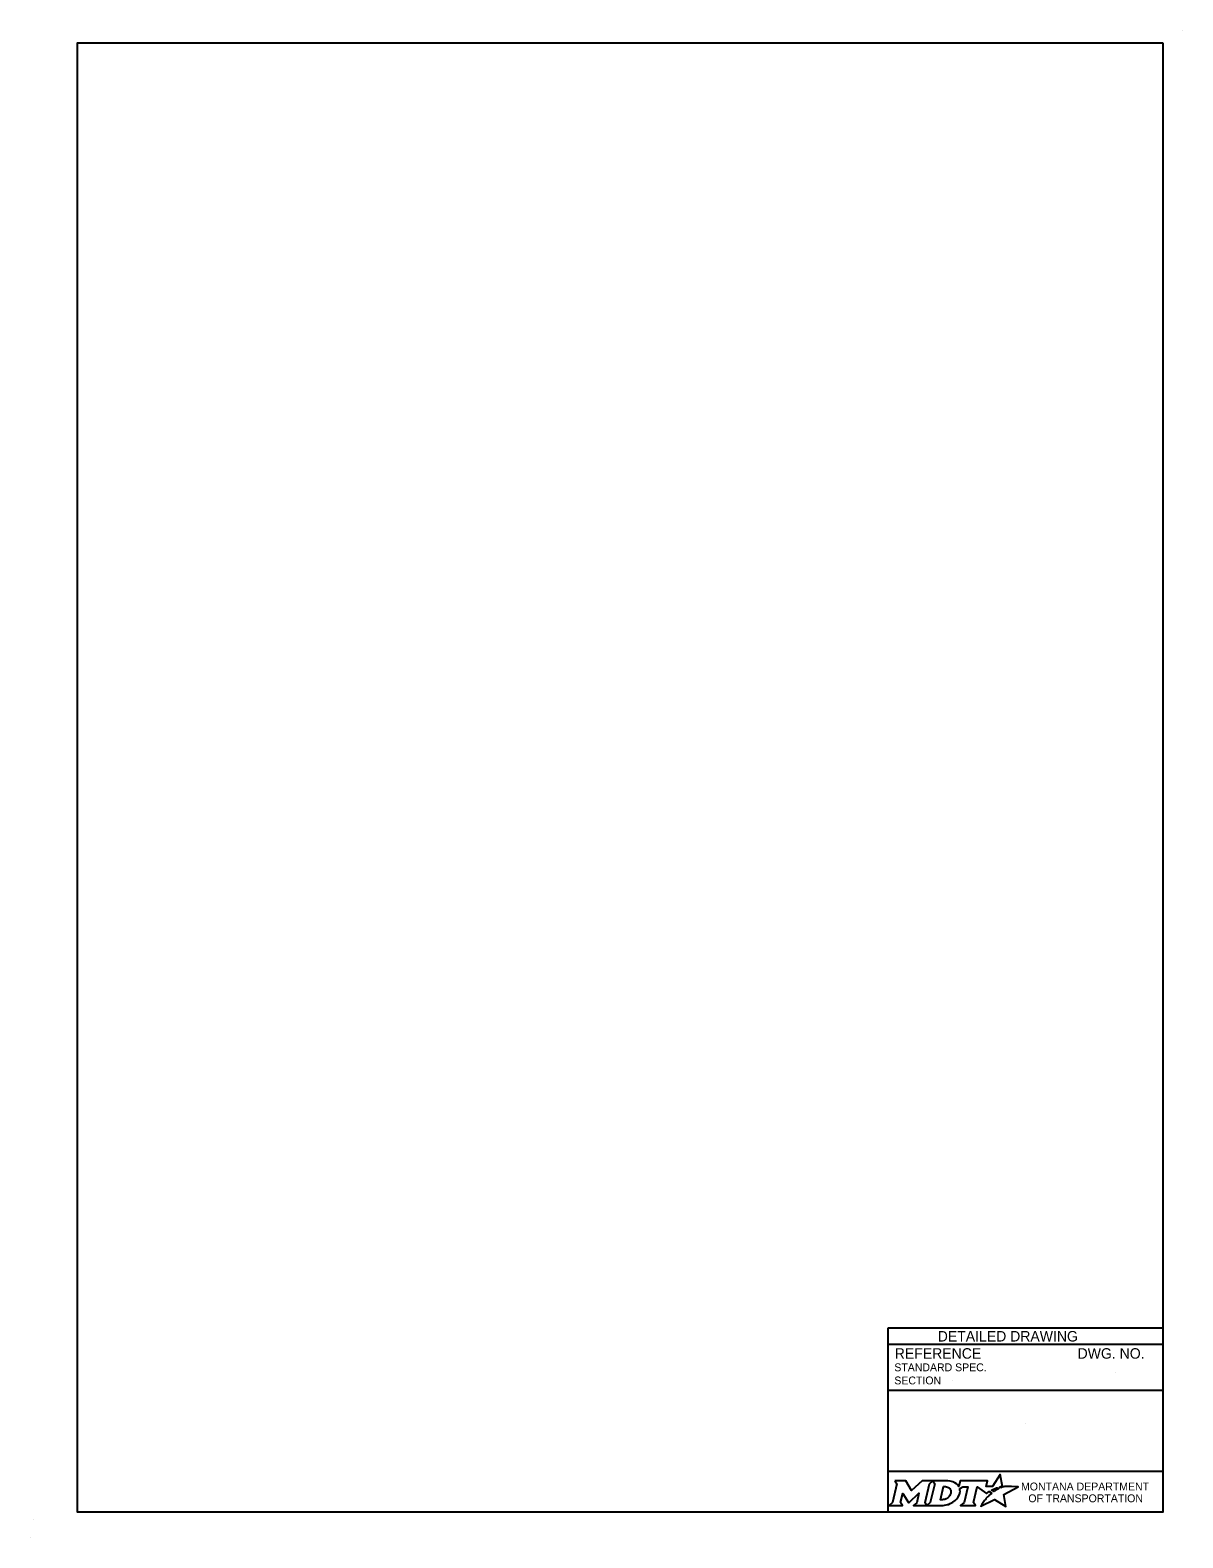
# Model space of a CAD drawing. Extents: x 49991.4 to 50021, y 49987.6 to 50011.4.
# Drawn here: x 49999.98 to 50008.76, y 49999.86 to 50011.36 of the extents above; entities that cross this region are included whole.
import ezdxf

# ---------------------------------------------------------------- set-up
doc = ezdxf.new("R2010")
doc.units = 0
doc.layers.add('Level 1', color=7, linetype='Continuous')
doc.layers.add('Level 2', color=7, linetype='Continuous')

msp = doc.modelspace()

# ---------------------------------------------------------------- linework, layer by layer
at = {"layer": 'Level 1'}
for p, q in [((50008.765, 50011.363), (50008.765, 50011.363)), ((49999.977, 49999.862), (49999.977, 49999.862))]:
    msp.add_line(p, q, dxfattribs=at)
msp.add_lwpolyline([(50008.615, 50011.263), (50000.336, 50011.263), (50000.336, 50000.062), (50008.615, 50000.062)], close=True, dxfattribs=at)
at = {"layer": 'Level 2'}
for p, q in [((50008.615, 50001.462), (50006.515, 50001.462)), ((50006.515, 50001.462), (50006.515, 50000.062)), ((50008.615, 50001.337), (50006.515, 50001.337)), ((50008.251, 50001.122), (50008.251, 50001.122)), ((50008.615, 50000.987), (50006.515, 50000.987)), ((50007.009, 50001.063), (50007.009, 50001.063)), ((50007.565, 50000.738), (50007.565, 50000.738)), ((50008.615, 50000.369), (50006.515, 50000.369)), ((50000, 50000), (50000, 50000))]:
    msp.add_line(p, q, dxfattribs=at)
for points in [[(50006.57, 50000.297), (50006.584, 50000.274), (50006.551, 50000.131), (50006.525, 50000.108), (50006.627, 50000.108), (50006.613, 50000.131), (50006.629, 50000.201), (50006.673, 50000.132), (50006.678, 50000.132), (50006.753, 50000.202), (50006.737, 50000.13), (50006.712, 50000.108), (50006.814, 50000.108), (50006.8, 50000.132), (50006.833, 50000.274)], [(50006.833, 50000.274), (50006.859, 50000.297), (50006.776, 50000.297), (50006.697, 50000.224), (50006.652, 50000.297), (50006.57, 50000.297)], [(50006.972, 50000.297), (50006.859, 50000.297), (50006.873, 50000.275), (50006.839, 50000.131), (50006.814, 50000.108), (50006.925, 50000.108)], [(50007.377, 50000.245), (50007.367, 50000.25), (50007.378, 50000.253), (50007.39, 50000.255), (50007.373, 50000.345), (50007.313, 50000.254), (50007.266, 50000.253), (50007.276, 50000.297), (50007.067, 50000.297), (50007.057, 50000.255), (50007.051, 50000.263)], [(50006.996, 50000.211), (50006.995, 50000.203), (50006.992, 50000.193), (50006.988, 50000.185), (50006.982, 50000.178), (50006.976, 50000.171), (50006.968, 50000.164), (50006.959, 50000.16), (50006.95, 50000.156), (50006.941, 50000.154), (50006.932, 50000.153), (50006.916, 50000.153), (50006.94, 50000.253), (50006.956, 50000.253), (50006.963, 50000.252), (50006.971, 50000.25), (50006.977, 50000.247), (50006.983, 50000.243), (50006.988, 50000.238), (50006.992, 50000.232), (50006.995, 50000.226), (50006.996, 50000.218), (50006.996, 50000.215), (50006.996, 50000.211)], [(50007.064, 50000.238), (50007.088, 50000.251), (50007.125, 50000.251), (50007.097, 50000.131), (50007.069, 50000.108), (50007.185, 50000.108), (50007.168, 50000.131), (50007.196, 50000.251), (50007.268, 50000.2), (50007.289, 50000.215), (50007.309, 50000.204)], [(50007.253, 50000.148), (50007.237, 50000.124), (50007.233, 50000.116), (50007.227, 50000.107), (50007.225, 50000.103), (50007.33, 50000.156), (50007.414, 50000.101), (50007.401, 50000.194), (50007.508, 50000.252), (50007.458, 50000.253), (50007.428, 50000.253), (50007.407, 50000.254), (50007.401, 50000.252), (50007.396, 50000.251), (50007.387, 50000.249), (50007.377, 50000.245)], [(50007.327, 50000.217), (50007.324, 50000.215), (50007.306, 50000.225), (50007.316, 50000.231), (50007.32, 50000.233), (50007.329, 50000.237), (50007.335, 50000.239), (50007.343, 50000.243), (50007.35, 50000.245), (50007.362, 50000.238), (50007.358, 50000.236), (50007.353, 50000.233), (50007.349, 50000.231), (50007.344, 50000.228), (50007.342, 50000.227), (50007.339, 50000.225), (50007.337, 50000.224), (50007.334, 50000.222), (50007.332, 50000.221), (50007.329, 50000.219), (50007.327, 50000.217)], [(50006.97, 50000.116), (50006.979, 50000.118), (50006.992, 50000.124), (50007.012, 50000.135)], [(50007.267, 50000.164), (50007.267, 50000.164)]]:
    msp.add_lwpolyline(points, dxfattribs=at)
for centre, radius, start, end in [((50006.951, 50000.236), 0.118, 300.9103, 339.1383), ((50006.995, 50000.219), 0.0709, 339.5329, 15.8582)]:
    msp.add_arc(centre, radius, start, end, dxfattribs=at)
for centre, major_axis, ratio, start_param, end_param in [((50006.97, 50000.25), (0.0834, -0.0037), 0.568097, 0.61298, 1.570796), ((50007.026, 50000.257), (0.0361, -0.0295), 0.469099, 1.225588, 1.570796), ((50007.276, 50000.174), (-0.0098, -0.0102), 0.016458, 3.141593, 6.279097), ((50007.297, 50000.194), (-0.0112, -0.0097), 0.021651, 3.157348, 6.283185), ((50006.925, 50000.257), (0, 0.148), 0.987302, 3.139398, 3.456847), ((50007.26, 50000.156), (-0.00694, -0.00806), 0.008222, 0, 3.137361)]:
    msp.add_ellipse(centre, major_axis=major_axis, ratio=ratio, start_param=start_param, end_param=end_param, dxfattribs=at)

# ---------------------------------------------------------------- texts
for s, height, p in [('DETAILED DRAWING', 0.0799, (50006.896, 50001.36)), ('REFERENCE', 0.08, (50006.568, 50001.229)), ('DWG. NO.', 0.08, (50007.962, 50001.229)), ('STANDARD SPEC.', 0.06, (50006.565, 50001.133)), ('SECTION', 0.06, (50006.565, 50001.033)), ('MONTANA DEPARTMENT', 0.06, (50007.531, 50000.224)), ('OF TRANSPORTATION', 0.06, (50007.587, 50000.134))]:
    msp.add_text(s, height=height, dxfattribs=at).set_placement(p)

doc.saveas('drawing.dxf')
